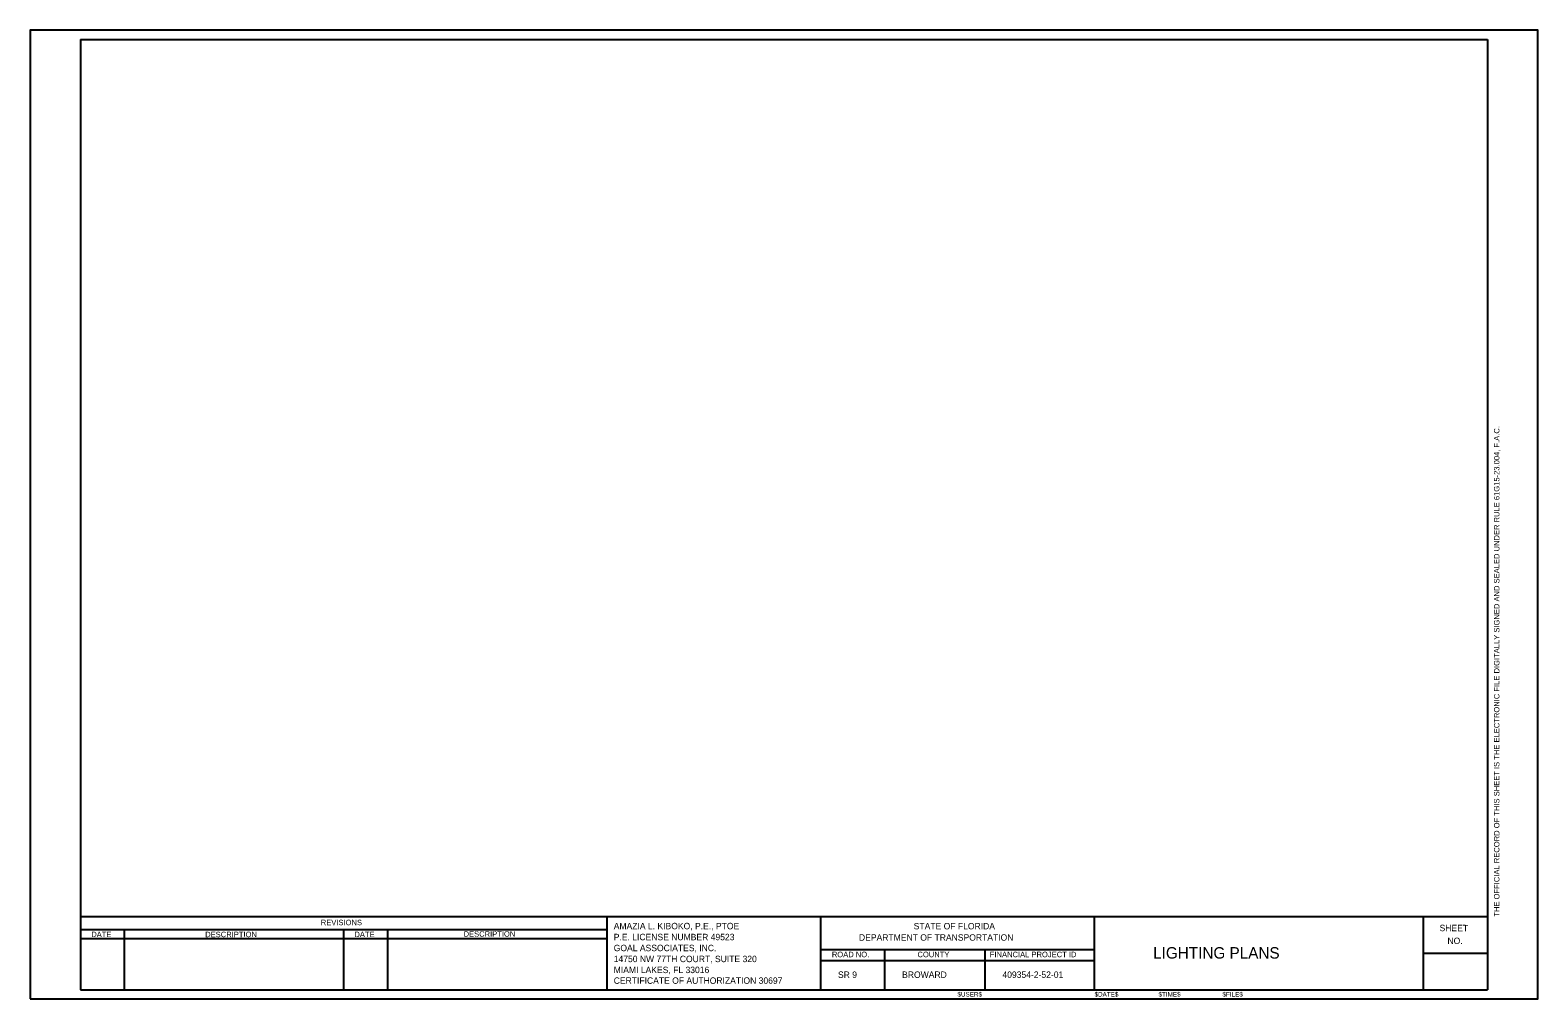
# Model space of a CAD drawing. Extents: x -816.7 to -800.2, y -2197.9 to -2187.3.
import ezdxf

# ---------------------------------------------------------------- set-up
doc = ezdxf.new("R2010")
doc.units = 0
for name, color, linetype in [('AdhocPoint_dp', 7, 'Continuous'), ('PlotBorder_dp', 7, 'Continuous'), ('SheetBorder_dp', 7, 'Continuous'), ('SheetLines_dp', 7, 'Continuous'), ('TextMinor', 7, 'Continuous'), ('TextMisc', 7, 'Continuous'), ('TextTitle', 7, 'Continuous')]:
    doc.layers.add(name, color=color, linetype=linetype)

msp = doc.modelspace()

# ---------------------------------------------------------------- linework, layer by layer
at = {"layer": 'AdhocPoint_dp'}
msp.add_line((-816.669, -2197.899), (-816.669, -2197.899), dxfattribs=at)
msp.add_line((-816.669, -2197.899), (-816.669, -2197.899), dxfattribs=at)
at = {"layer": 'PlotBorder_dp'}
msp.add_lwpolyline([(-816.669, -2197.899), (-800.169, -2197.899), (-800.169, -2187.299), (-816.669, -2187.299)], close=True, dxfattribs=at)
at = {"layer": 'SheetBorder_dp'}
for p, q in [((-816.119, -2187.399), (-816.119, -2197.799)), ((-816.119, -2187.399), (-800.719, -2187.399)), ((-800.719, -2187.399), (-800.719, -2197.799)), ((-816.119, -2196.999), (-800.719, -2196.999)), ((-816.119, -2197.799), (-800.719, -2197.799))]:
    msp.add_line(p, q, dxfattribs=at)
at = {"layer": 'SheetLines_dp'}
for p, q in [((-816.119, -2197.139), (-810.359, -2197.139)), ((-815.639, -2197.139), (-815.639, -2197.799)), ((-813.239, -2197.139), (-813.239, -2197.799)), ((-812.759, -2197.139), (-812.759, -2197.799)), ((-810.359, -2196.999), (-810.359, -2197.799)), ((-808.019, -2196.999), (-808.019, -2197.799)), ((-805.019, -2197.799), (-805.019, -2196.999)), ((-801.419, -2197.799), (-801.419, -2196.999)), ((-816.119, -2197.239), (-810.359, -2197.239)), ((-808.019, -2197.359), (-805.019, -2197.359)), ((-807.319, -2197.359), (-807.319, -2197.799)), ((-806.219, -2197.359), (-806.219, -2197.799)), ((-801.419, -2197.399), (-800.719, -2197.399)), ((-808.019, -2197.479), (-805.019, -2197.479))]:
    msp.add_line(p, q, dxfattribs=at)

# ---------------------------------------------------------------- texts
at = {"layer": 'TextMinor'}
msp.add_text('$USER$', height=0.05, dxfattribs=at).set_placement((-806.52, -2197.874))
for s, p in [('$DATE$', (-805.02, -2197.874)), ('$TIME$', (-804.32, -2197.874)), ('$FILE$', (-803.62, -2197.874))]:
    msp.add_text(s, height=0.05, rotation=360, dxfattribs=at).set_placement(p)
at = {"layer": 'TextMisc'}
for s, height, rotation, p in [('THE OFFICIAL RECORD OF THIS SHEET IS THE ELECTRONIC FILE DIGITALLY SIGNED AND SEALED UNDER RULE 61G15-23.004, F.A.C.', 0.06, 90, (-800.589, -2196.999)), ('SHEET', 0.07, 359.8607, (-801.244, -2197.158)), ('DATE', 0.06, 359.8693, (-816, -2197.223)), ('DESCRIPTION', 0.06, 0.0498, (-814.753, -2197.224)), ('DATE', 0.06, 359.8693, (-813.12, -2197.223)), ('DESCRIPTION', 0.06, 0.0498, (-811.925, -2197.219)), ('NO.', 0.07, 359.8607, (-801.158, -2197.298))]:
    msp.add_text(s, height=height, rotation=rotation, dxfattribs=at).set_placement(p)
for s, height, p in [('REVISIONS', 0.06, (-813.488, -2197.093)), ('STATE OF FLORIDA', 0.07, (-806.999, -2197.138)), ('DEPARTMENT OF TRANSPORTATION', 0.07, (-807.598, -2197.262)), ('ROAD NO.', 0.06, (-807.895, -2197.443)), ('COUNTY', 0.06, (-806.958, -2197.443)), ('FINANCIAL PROJECT ID', 0.06, (-806.166, -2197.443)), ('        LIGHTING PLANS         ', 0.125, (-804.75, -2197.458)), (' SR 9  ', 0.07, (-807.854, -2197.669)), ('  BROWARD   ', 0.07, (-807.178, -2197.669)), ('409354-2-52-01', 0.07, (-806.028, -2197.669))]:
    msp.add_text(s, height=height, dxfattribs=at).set_placement(p)
at = {"layer": 'TextTitle'}
for s, p in [('AMAZIA L. KIBOKO, P.E., PTOE', (-810.282, -2197.137)), ('P.E. LICENSE NUMBER 49523', (-810.282, -2197.257)), ('GOAL ASSOCIATES, INC.', (-810.282, -2197.377)), ('14750 NW 77TH COURT, SUITE 320', (-810.282, -2197.497)), ('MIAMI LAKES, FL 33016', (-810.282, -2197.617)), ('CERTIFICATE OF AUTHORIZATION 30697', (-810.282, -2197.734))]:
    msp.add_text(s, height=0.07, dxfattribs=at).set_placement(p)

doc.saveas('drawing.dxf')
